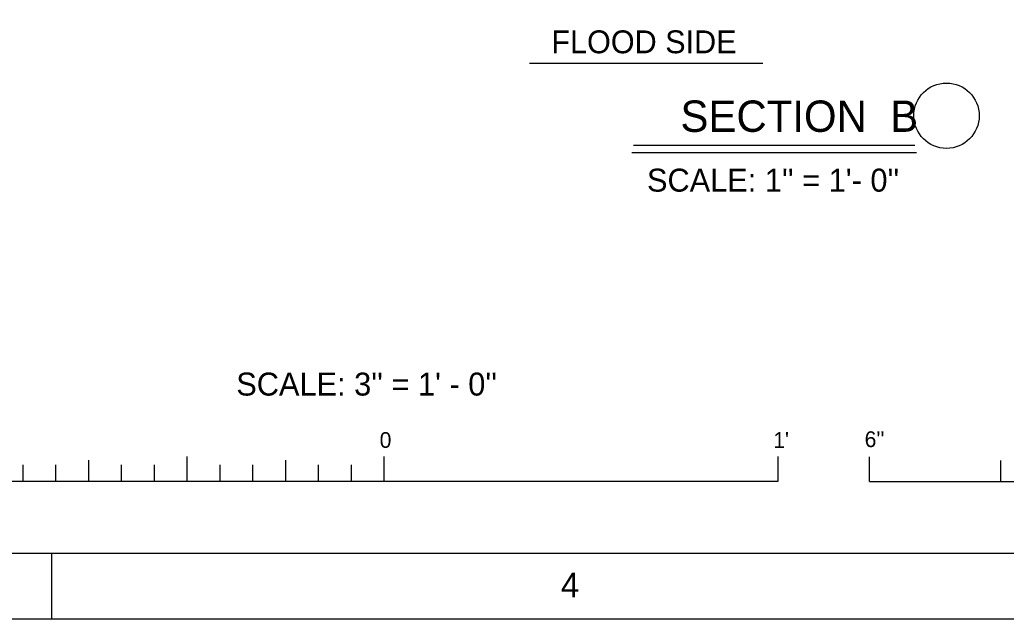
# Model space of a CAD drawing. Extents: x 22369.6 to 22428.3, y 22369.6 to 22415.
# Drawn here: x 22402.68 to 22412.7, y 22369.62 to 22375.71 of the extents above; entities that cross this region are included whole.
import ezdxf

# ---------------------------------------------------------------- set-up
doc = ezdxf.new("R2010")
doc.units = 0
for name, color, linetype in [('Level 1', 7, 'Continuous'), ('Level 10', 7, 'Continuous'), ('Level 2', 7, 'Continuous'), ('Level 3', 7, 'Continuous'), ('Level 7', 7, 'Continuous'), ('Level 9', 7, 'Continuous')]:
    doc.layers.add(name, color=color, linetype=linetype)

msp = doc.modelspace()

# ---------------------------------------------------------------- linework, layer by layer
at = {"layer": 'Level 1'}
msp.add_lwpolyline([(22369.621, 22414.965), (22428.288, 22414.965), (22428.288, 22369.621), (22369.621, 22369.621)], close=True, dxfattribs=at)
at = {"layer": 'Level 10'}
for p, q in [((22407.856, 22375.268), (22410.226, 22375.268)), ((22408.912, 22374.435), (22411.771, 22374.435)), ((22408.897, 22374.361), (22411.786, 22374.361)), ((22403.008, 22369.621), (22403.008, 22370.293))]:
    msp.add_line(p, q, dxfattribs=at)
at = {"layer": 'Level 3'}
msp.add_circle((22412.091, 22374.733), 0.332, dxfattribs=at)
at = {"layer": 'Level 7'}
for p, q in [((22404.382, 22371.022), (22404.382, 22371.272)), ((22406.382, 22371.022), (22406.382, 22371.272)), ((22410.382, 22371.022), (22410.382, 22371.272)), ((22402.716, 22371.022), (22402.716, 22371.188)), ((22403.049, 22371.022), (22403.049, 22371.188)), ((22403.382, 22371.022), (22403.382, 22371.236)), ((22403.716, 22371.022), (22403.716, 22371.188)), ((22404.049, 22371.022), (22404.049, 22371.188)), ((22404.716, 22371.022), (22404.716, 22371.188)), ((22405.049, 22371.022), (22405.049, 22371.188)), ((22405.382, 22371.022), (22405.382, 22371.236)), ((22405.716, 22371.022), (22405.716, 22371.188)), ((22406.049, 22371.022), (22406.049, 22371.188)), ((22411.308, 22371.02), (22411.308, 22371.27)), ((22412.641, 22371.02), (22412.641, 22371.234)), ((22402.382, 22371.022), (22410.382, 22371.022)), ((22411.308, 22371.02), (22419.308, 22371.02))]:
    msp.add_line(p, q, dxfattribs=at)
at = {"layer": 'Level 9'}
msp.add_line((22371.621, 22370.293), (22423.952, 22370.293), dxfattribs=at)

# ---------------------------------------------------------------- texts
at = {"layer": 'Level 1'}
msp.add_text('4', height=0.25, dxfattribs=at).set_placement((22408.176, 22369.845))
at = {"layer": 'Level 10'}
msp.add_text('FLOOD SIDE', height=0.2322, dxfattribs=at).set_placement((22408.079, 22375.367))
at = {"layer": 'Level 2'}
for s, p in [('0', (22406.336, 22371.361)), ("1'", (22410.332, 22371.361)), ("6''", (22411.26, 22371.369))]:
    msp.add_text(s, height=0.16, dxfattribs=at).set_placement(p)
at = {"layer": 'Level 3'}
msp.add_text('SECTION  B', height=0.3184, dxfattribs=at).set_placement((22409.39, 22374.569))
at = {"layer": 'Level 7'}
for s, p in [("SCALE: 1'' = 1'- 0''", (22409.05, 22373.962)), ("SCALE: 3'' = 1' - 0''", (22404.88, 22371.892))]:
    msp.add_text(s, height=0.23333, dxfattribs=at).set_placement(p)

doc.saveas('drawing.dxf')
